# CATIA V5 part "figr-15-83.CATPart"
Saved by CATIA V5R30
Part number: Part1
Bounding box of the stored display mesh (mm): x 0 to 27, y -46 to 46, z -30 to 30
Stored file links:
  D:\PROJECTS\CATIA V56R 2020\Resources\Parts File\c15_catia_v5_6r2020_prt\figr-15-83.CATPart
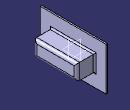
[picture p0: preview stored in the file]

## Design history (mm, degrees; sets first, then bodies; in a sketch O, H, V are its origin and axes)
SheetMetalParameters1: Thickness 2, BendRadius 4, KFactor 0.400515 {= log(min(100,max(20*SheetMetalParameters1.BendRadius,SheetMetalParameters1.Thickness)/SheetMetalParameters1.Thickness))/log(100)/2}, ReliefRadialLength 1, ReliefAxialLength 2, MinimumBendRadius 0
Body1 (main body)
  Sketch1 on yz-plane, origin (0, 0, 0), H (0, 1, 0), V (0, 0, 1)
    line L1 (46, 30) -> (46, -30)
    line L2 (46, -30) -> (-46, -30)
    line L3 (-46, -30) -> (-46, 30)
    line L4 (-46, 30) -> (46, 30)
    vertical: L1 V, L3 V
    horizontal: L2 H, L4 H
    equidistance: L1 L3 O, L2 L4 O
  Wall1: Thickness 2, Profile Sketch1, OffsetValue 0
  Sketch2 on face of Wall1, origin (2, 0, 0), H (0, 1, 0), V (0, 0, 1)
    line L1 (28, 9) -> (28, -9)
    line L2 (28, -9) -> (-28, -9)
    line L3 (-28, -9) -> (-28, 9)
    line L4 (-28, 9) -> (28, 9)
    vertical: L1 V, L3 V
    horizontal: L2 H, L4 H
    equidistance: L1 L3 O, L2 L4 O
  d_Stamp1: NewRoot_AttribNormalisation "No Standard", Stamp_FilletRadius 2, Stamp_IntersectFilletRadius 2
